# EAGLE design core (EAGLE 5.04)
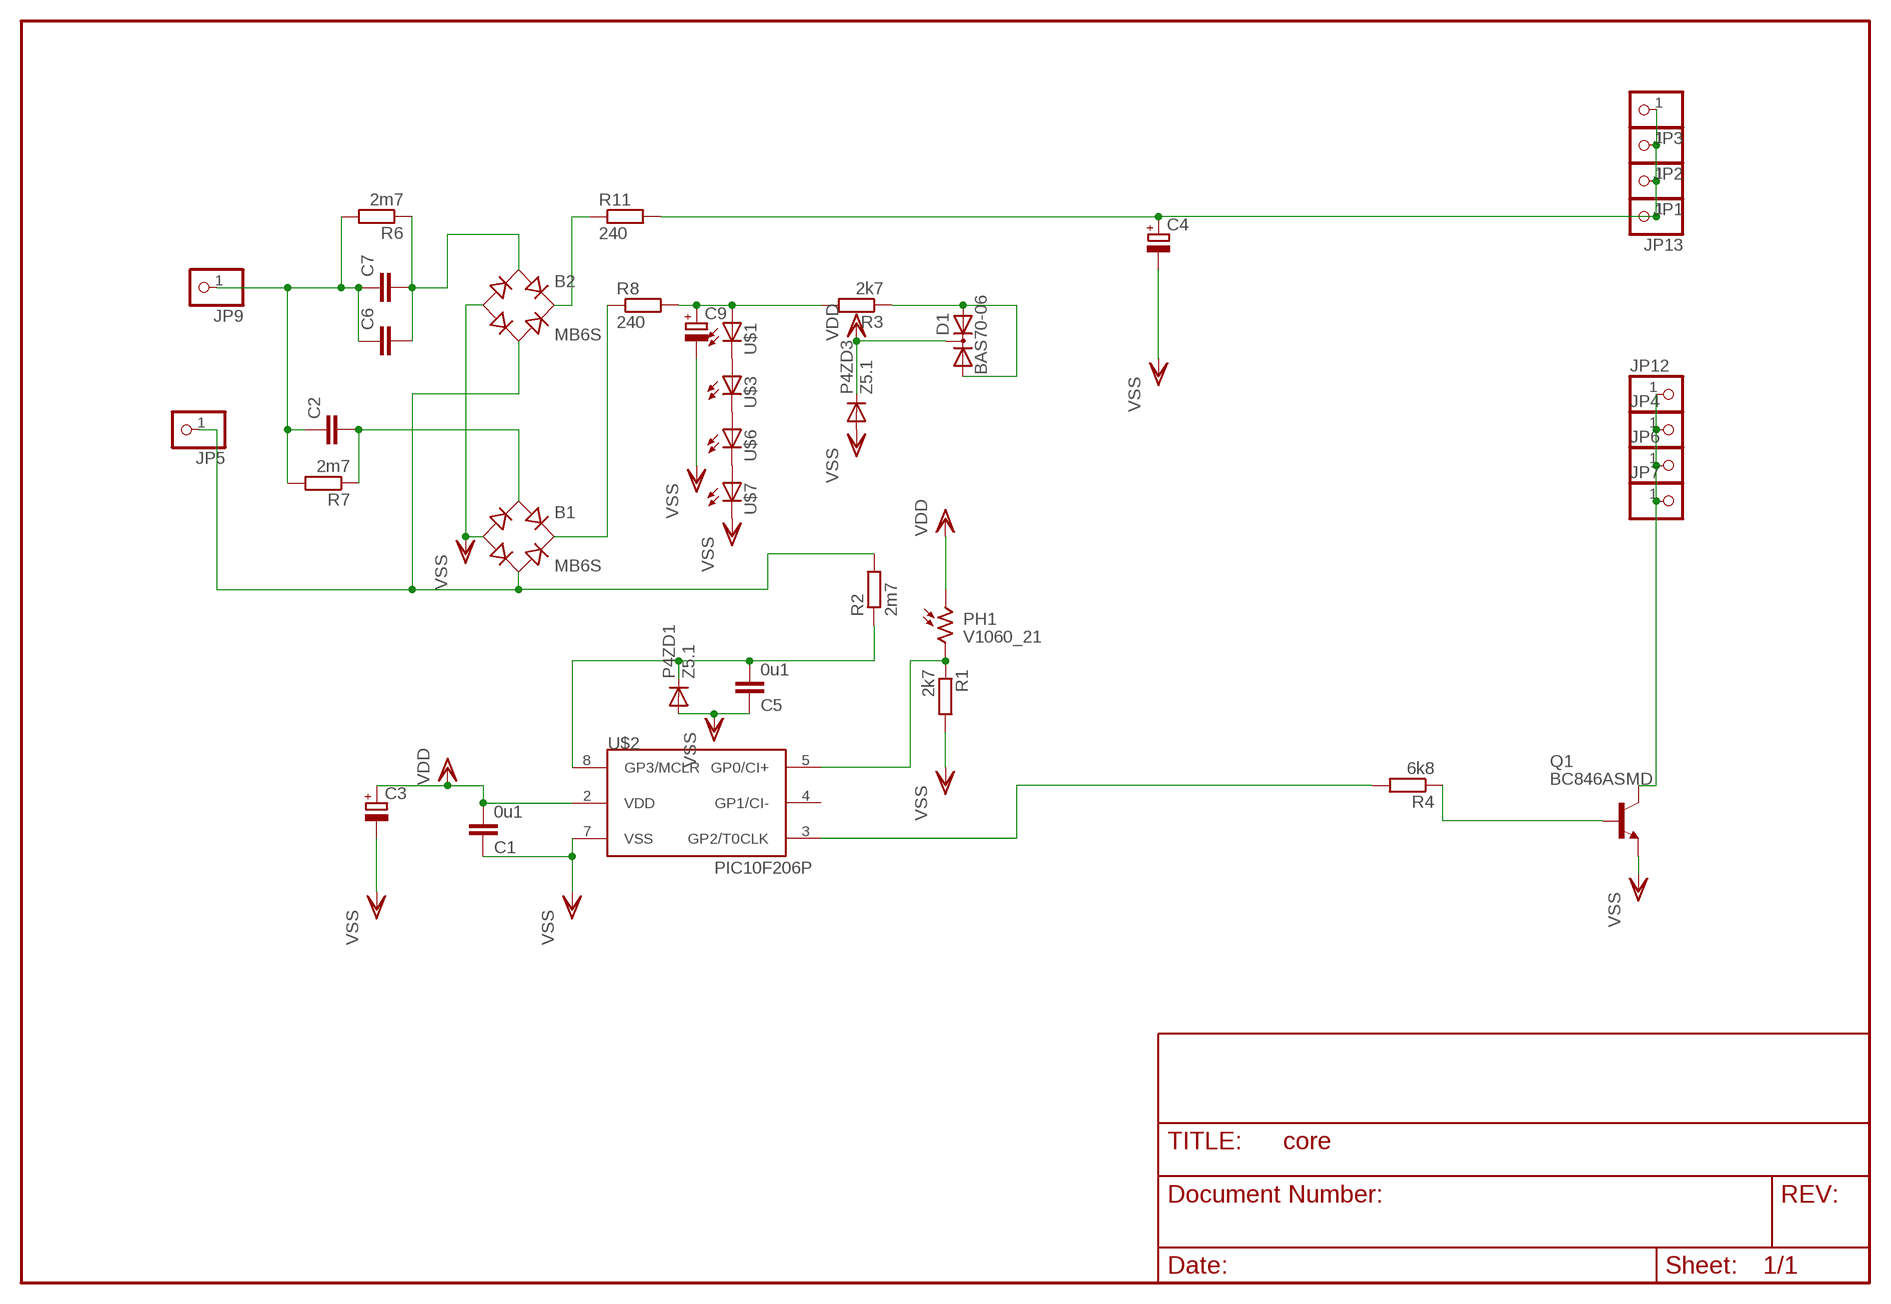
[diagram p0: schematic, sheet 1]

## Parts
B1  MB6S  [SOIC-4]
B2  MB6S  [SOIC-4]
C1  0u1  C-EUC1206  [C1206]
C2  C-EU150-054X183  [C150-054X183]
C3  CPOL-EU5-13  [2,5-5-FLAT]
C4  CPOL-EUTT5D11L  [TT5D11L]
C5  0u1  C-EUC1206  [C1206]
C6  C-EU150-064X183  [C150-064X183]
C7  C-EU150-054X183  [C150-054X183]
C9  CPOL-EUTT5D11L  [TT5D11L]
D1  BAS70-06  [SOT23]
JP1  PINHD-1X1  [1X01]
JP2  PINHD-1X1  [1X01]
JP3  PINHD-1X1  [1X01]
JP4  PINHD-1X1  [1X01]
JP5  PINHD-1X1  [1X01]
JP6  PINHD-1X1  [1X01]
JP7  PINHD-1X1  [1X01]
JP9  PINHD-1X1  [1X01]
JP12  PINHD-1X1  [1X01]
JP13  PINHD-1X1  [1X01]
P4ZD1  Z5.1  DIODE-MINIMELF  [MINIMELF]
P4ZD3  Z5.1  DIODE-MINIMELF  [MINIMELF]
PH1  V1060_21  [TO-5_V10]
Q1  BC846ASMD  [SOT23]
R1  2k7  R-EU_R0805  [R0805]
R2  2m7  R-EU_R1206  [R1206]
R3  2k7  R-EU_R0805  [R0805]
R4  6k8  R-EU_R0805  [R0805]
R6  2m7  R-EU_R1206  [R1206]
R7  2m7  R-EU_R1206  [R1206]
R8  240  R-EU_R1206  [R1206]
R11  240  R-EU_R1206  [R1206]
U$1  LED5MM  [LED5MM]
U$2  PIC10F206P  [DIL8]
U$3  LED5MM  [LED5MM]
U$6  LED5MM  [LED5MM]
U$7  LED5MM  [LED5MM]

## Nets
D+: C4.+ JP1.1 JP2.1 JP3.1 JP13.1 R11.2
D-: JP4.1 JP6.1 JP7.1 JP12.1 Q1.3(C)
N$1: C5.2 P4ZD1.C R2.1 U$2.8(GP3/MCLR)
N$2: B1.+ R8.1
N$3: B1.~2(AC2) B2.~2(AC2) JP5.1 R2.2
N$4: C9.+ R3.2 R8.2 U$1.A
N$5: D1.1(A1) D1.2(A2) R3.1
N$6: C2.1 C6.1 C7.1 JP9.1 R6.2 R7.2
N$7: U$1.K(C) U$3.A
N$8: B1.~1(AC1) C2.2 R7.1
N$9: B2.~1(AC1) C6.2 C7.2 R6.1
N$10: U$3.K(C) U$6.A
N$11: B2.+ R11.1
N$12: Q1.1(B) R4.1
N$15: R4.2 U$2.3(GP2/T0CLK)
N$16: U$6.K(C) U$7.A
N$17: PH1.2 R1.1 U$2.5(GP0/CI+)
VDD: C1.2 C3.+ D1.3(C) P4ZD3.C PH1.1 U$2.2(VDD)
VSS: B1.- B2.- C1.1 C3.- C4.- C5.1 C9.- P4ZD1.A P4ZD3.A Q1.2(E) R1.2 U$2.7(VSS) U$7.K(C)
Unconnected: U$2.4(GP1/CI-)

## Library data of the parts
B1 B2 = rectifier:MB*S: Bridge Rectifier Source: http://www.fairchildsemi.com/ds/MB/MB6S.pdf
C1 C5 = rcl:C-EU: CAPACITOR, European symbol
C2 C6 C7 = rcl-2:C-EU: CAPACITOR, European symbol
C3 C4 C9 = rcl-2:CPOL-EU: POLARIZED CAPACITOR, European symbol
D1 = diode:BAS70-06: Silicon Schottky Diodes General-purpose diode for high-speed switching
JP1-JP7 JP9 JP12 JP13 = pinhead(2):PINHD-1X1: PIN HEADER
P4ZD1 P4ZD3 = diode:DIODE-: DIODE
PH1 = photo-elements:?1060*: Sensor Street Light control
Q1 = transistor-npn:BC846*: NPN Transistor
R1-R4 R6-R8 R11 = rcl-2:R-EU_: RESISTOR, European symbol
U$1 U$3 U$6 U$7 = led(3):LED: LED
U$2 = microchip-3:PIC10F2*: uPC nW 0,25/0,5k Program Flash memory Comparator

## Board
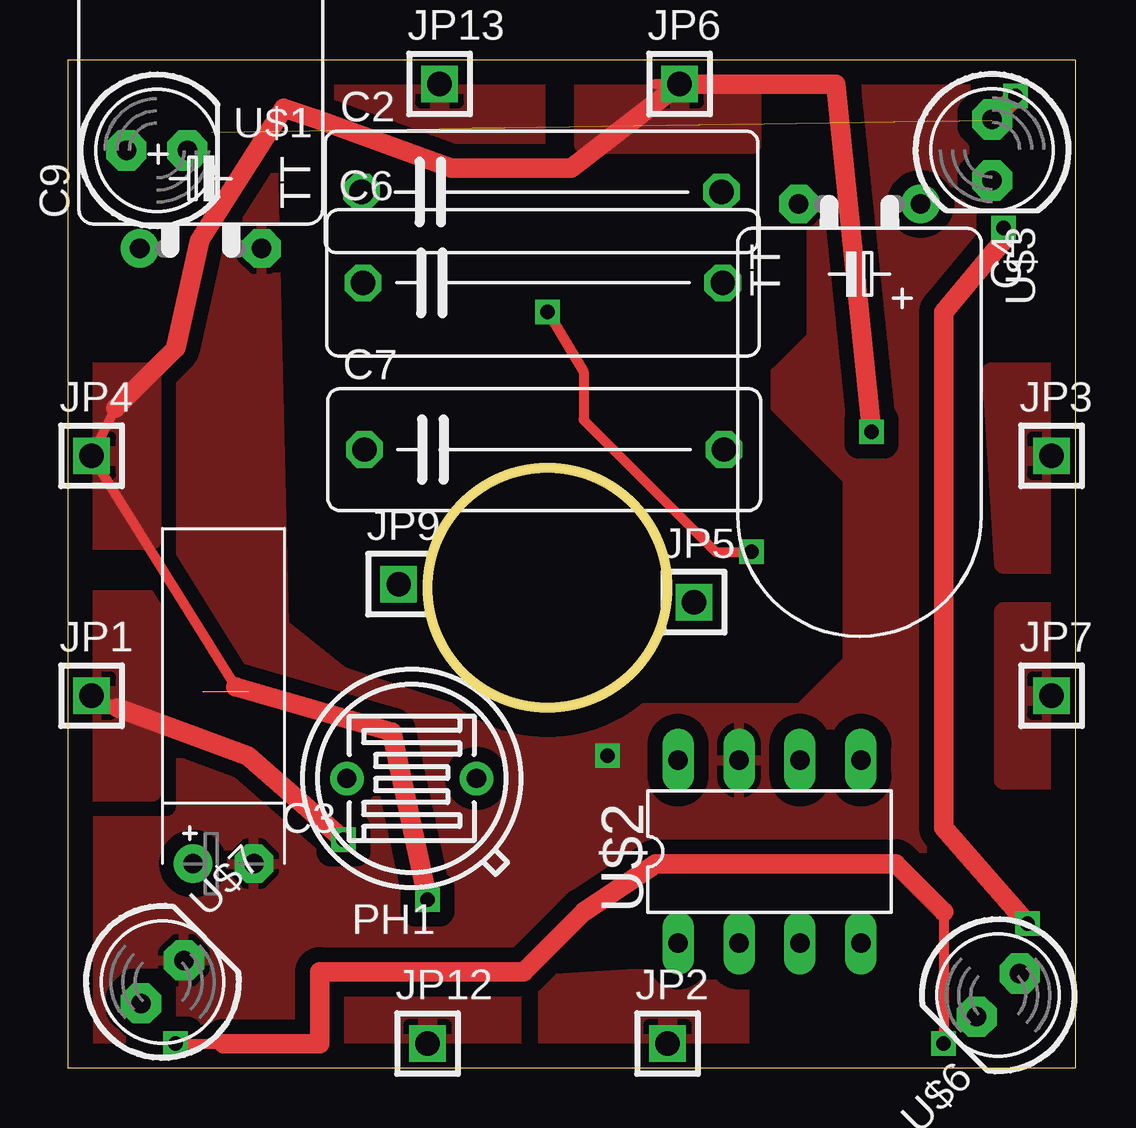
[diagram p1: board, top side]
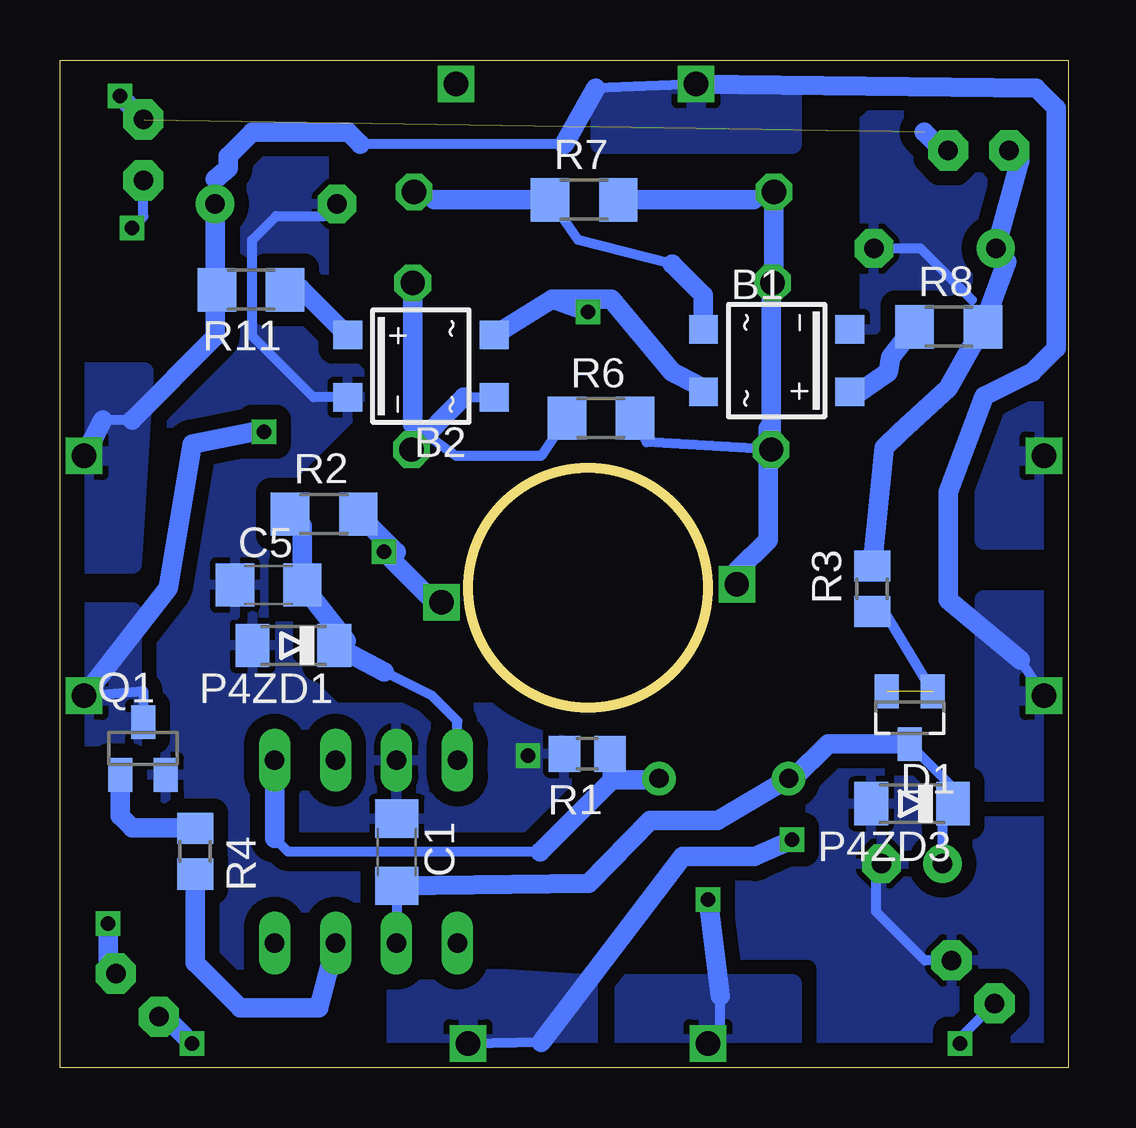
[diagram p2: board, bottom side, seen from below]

Size 42 x 42 mm. Coordinates in mm from the lower left corner, seen from the top.
Outline: 0,0 42,0 42,42 0,42 0,0
Outline: circle at 20,20 radius 5
Copper layers (1*16): Top 0.035mm / dielectric 1.5mm / Bottom 0.035mm
Design rules "default": minimum track width 10mil, minimum drill 24mil, track to track 8mil, track to pad 8mil, pad to pad 8mil, via to via 8mil, smd to smd 8mil, copper to edge 40mil, drill to drill 8mil, minimum pad ring 10mil, minimum via ring 8mil, stop-mask expansion 4mil, vias tented up to drill 0mil, thermal gap 10mil

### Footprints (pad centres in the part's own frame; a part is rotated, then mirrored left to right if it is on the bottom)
SOIC-4 = smd 1.2 x 1.2: + 1.3,3.05; - -1.3,3.05; ~1 -1.3,-3.05; ~2 1.3,-3.05
C1206 = smd 1.6 x 1.8: 1 -1.4,0; 2 1.4,0
C150-054X183 = drill 1.016 octagon: 1 -7.493,0; 2 7.493,0
2,5-5-FLAT = drill 0.813 pad 1.6 round: + -1.27,0 | drill 0.813 pad 1.6 octagon: - 1.27,0
TT5D11L = drill 0.813 pad 1.6 round: + -2.54,0 | drill 0.813 pad 1.6 octagon: - 2.54,0
C150-064X183 = drill 1.016 octagon: 1 -7.493,0; 2 7.493,0
SOT23 = smd 1 x 1.4: 1 -0.95,-1.1; 2 0.95,-1.1; 3 0,1.1
1X01 = drill 1.016 square: 1 0,0
MINIMELF = smd 1.4 x 1.8: A 1.7,0; C -1.7,0
TO-5_V10 = drill 0.8 pad 1.4 round: 1 -2.7,0; 2 2.7,0
R0805 = smd 1.3 x 1.5: 1 -0.95,0; 2 0.95,0
R1206 = smd 1.6 x 1.803: 1 -1.422,0; 2 1.422,0
LED5MM = drill 0.813 pad 1.676 octagon: A -1.27,0; K 1.27,0
DIL8 = drill 0.813 long: 1 -3.81,-3.81; 2 -1.27,-3.81; 3 1.27,-3.81; 4 3.81,-3.81; 5 3.81,3.81; 6 1.27,3.81; 7 -1.27,3.81; 8 -3.81,3.81

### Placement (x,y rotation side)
B1  12.14,29.47 270 bottom
B2  26.96,29.24 90 bottom
C1  27.97,8.97 270 bottom
C2  19.75,36.5 0 top
C3  6.5,8.5 0 top
C4  33,36 180 top
C5  33.31,20.12 0 bottom
C6  19.81,32.71 0 top
C7  19.86,25.76 0 top
C9  5.55,34.14 0 top
D1  6.59,14.58 180 bottom
JP1  1,15.5 0 top
JP2  25,1 0 top
JP3  41,25.5 0 top
JP4  1,25.5 0 top
JP5  26.1,19.4 0 top
JP6  25.5,41 0 top
JP7  41,15.5 0 top
JP9  13.8,20.15 0 top
JP12  15,1 0 top
JP13  15.5,41 0 top
P4ZD1  32.27,17.59 180 bottom
P4ZD3  6.5,11 180 bottom
PH1  14.34,12.05 0 top
Q1  38.54,13.3 0 bottom
R1  20.03,13.08 180 bottom
R2  30.99,23.07 0 bottom
R3  8.16,19.96 90 bottom
R4  36.37,9.01 270 bottom
R6  19.46,27.07 0 bottom
R7  20.16,36.17 0 bottom
R8  4.97,30.88 0 bottom
R11  34.04,32.42 180 bottom
U$1  3.72,38.23 0 top
U$2  29.25,9 0 top
U$3  38.53,38.25 270 top
U$6  38.78,3.02 225 top
U$7  3.96,3.57 45 top

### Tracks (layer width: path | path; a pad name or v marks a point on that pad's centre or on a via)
D+  (via drill 0.6)
  Top 0.406: 2.09,15 JP1.1
  Top 0.813: v11.5,9.5 7.5,13 2.09,15
  Bottom 0.406: 35.54,32.5 R11.2 | 39,27 40.21,27 | 21.94,1.06 JP2.1 | JP1.1 2,17 | JP13.1 19.68,40.82 | 21,38.5 29.5,38.5 | 35.54,37.04 C4.+
  Bottom 0.813: C4.+ 35.54,32.5 35.54,30.46 39,27 | 40.21,27 JP3.1 | 21.94,1.06 16.05,8.8 13.05,8.8 v11.5,9.5 | JP13.1 1.32,40.82 0.5,40 0.5,30 1.5,29 3.5,28 5,24 5,19.5 2,17 | 19.68,40.82 21,38.5 | 35.54,37.04 35,37.5 35,38 34,39 30,39 29.5,38.5
  pour Bottom (isolate 0.61, rank 2): 20,3.5 20,0.5 28,0.5 28,1 28,4
  pour Top (isolate 0.61, rank 2): 20,3.5 20,0.5 28,0.5 28,1 28,4
  pour Top (isolate 0.61, rank 2): 39,21 42,21 42,29 41.5,29 38.5,29
  pour Top (isolate 0.61, rank 2): 0.5,11.5 3.5,11.5 3.5,19.5 3,19.5 0,19.5
  pour Top (isolate 0.61, rank 2): 19.5,38.5 19.5,41.5 11.5,41.5 11.5,41 11.5,38
  pour Bottom (isolate 0.61, rank 2): 19.5,38.5 19.5,41.5 11.5,41.5 11.5,38.5
  pour Bottom (isolate 0.61, rank 2): 39,21 42,21 42,29 41.5,29 38.5,29
  pour Bottom (isolate 0.61, rank 2): 0.5,11.5 3.5,11.5 3.5,19.5 3,19.5 0,19.5
D-  (via drill 0.6)
  Top 0.406: 7,15.86 JP4.1 2,27.5 | JP6.1 24.51,41
  Top 0.813: v15,7 13.5,14 7,15.86 | 2,27.5 4.5,30 5.5,34.5 9,40 10.5,39.5 16,37.5 20.99,37.5 JP6.1 32,41 v33.5,26.5
  Bottom 0.406: JP12.1 14.5,1.5 14.5,3 | v33.5,26.5 34,26.5 | Q1.3 38.54,15.7 JP7.1
  Bottom 0.813: 14.5,3 v15,7 | JP7.1 37.5,20 36.5,26 34,26.5
  pour Bottom (isolate 0.61): 11.5,0 11.5,3.5 18.5,3.5 18.5,0
  pour Top (isolate 0.61): 11.5,0 11.5,3.5 18.5,3.5 18.5,0
  pour Top (isolate 0.61): 42.5,12 39,12 39,19 42.5,19
  pour Top (isolate 0.61): 28.5,42 28.5,38.5 21.5,38.5 21.5,42
  pour Top (isolate 0.61): 3.5,22 0,22 0,29 3.5,29
  pour Bottom (isolate 0.61): 42.5,12 39,12 39,19 42.5,19
  pour Top (isolate 0.61): 28.5,42 28.5,38.5 21.5,38.5 21.5,42
  pour Bottom (isolate 0.61): 3.5,22 0,22 0,29 3.5,29
N$1
  Bottom 0.406: U$2.8 25.44,14.44 26.5,15.5 28.48,16.5 | P4ZD1.C 30.07,17.78 | 31.91,22.57 R2.1
  Bottom 0.813: 28.48,16.5 P4ZD1.C | 30.07,17.78 C5.2 31.91,22.57
N$2
  Bottom 0.406: 8.92,28 B1.+
  Bottom 0.813: R8.1 7.39,29.61 7.5,29 8.92,28
N$3  (via drill 0.6)
  Top 0.406: v28.5,21.5 27,21.5 21.5,27 21.5,29 v20,31.5
  Bottom 0.406: B1.~2 15.52,28.5 | 26.4,19.4 JP5.1 | R2.2 | v28.5,21.5 28,21.5
  Bottom 0.813: 21.5,32.04 19.04,32.04 16.5,29 15.52,28.5 | 21.5,32.04 B2.~2 | v28.5,21.5 26.4,19.4 | 21.5,32.04 v20,31.5 | 28,21.5 R2.2
N$4
  Bottom 0.406: 2.55,33.6 C9.+ | 2.01,37.78 U$1.A
  Bottom 0.813: R3.2 7.67,25.84 7,26.5 5,28.33 R8.2 2.55,33.6 | C9.+ 2.01,37.78
N$5  (1 unrouted)
  Bottom 0.406: D1.1 7.64,18.99 R3.1
N$6
  Bottom 0.406: JP9.1 13.8,20.7 | 12.5,26.63 C7.1 17.56,26.07 R6.2 | 12.37,32.16 C6.1 12.26,32.27 | C2.1 13.09,36.17
  Bottom 0.813: 13.8,20.7 12.5,22 12.5,26.63 | C7.1 12.37,32.16 | 12.26,32.27 C2.1 | 13.09,36.17 R7.2
N$7  (via drill 0.6)  (1 unrouted)
  Top 0.406: U$3.A 38.5,39.5
  Top 0.813: 38.5,39.5 v39.5,40.5
  Bottom 0.813: U$1.K 5.23,38.23 6,39 | v39.5,40.5 38.5,39.5
N$8
  Bottom 0.406: 16.5,33.5 20.41,34.5 R7.1 | 26.41,36.17 C2.2
  Bottom 0.813: B1.~1 15.19,32.19 16.5,33.5 | R7.1 26.41,36.17
N$9
  Bottom 0.406: R6.1 21.95,25.5 25.5,25.5 27.26,26.76 C7.2 27.3,26.81 | 25.17,27.94 B2.~1
  Bottom 0.813: 27.3,26.81 C6.2 | C7.2 25.17,27.94
N$10  (via drill 0.6)
  Top 0.406: 39,34.5 v39,35
  Top 0.813: 39,34.5 36.5,31.5 36.5,10 v40,6
  Bottom 0.406: U$3.K 38.53,35.47 v39,35
  Bottom 0.813: v40,6 40,4.24 U$6.A
N$11
  Bottom 0.406: B2.+ 30.04,30.54 | 32,32.5 32.54,32.5 R11.1
  Bottom 0.813: 30.04,30.54 32,32.5
N$12
  Bottom 0.406: R4.1 36.41,10
  Bottom 0.813: Q1.1 39.49,10.49 39,10 36.41,10
N$15
  Bottom 0.813: R4.2 36.37,4.37 34.5,2.5 31.21,2.5 U$2.3
N$16  (via drill 0.6)
  Top 0.406: 36.5,6.5 v36.5,1 | v4.5,1 6.5,1
  Top 0.813: 36.5,6.5 34.5,8.5 24.5,8.5 21.5,6.5 19,4 10.5,4 10.5,1 6.5,1
  Bottom 0.406: 37.62,2.12 U$6.K | v4.5,1 4.5,1.23 U$7.A
  Bottom 0.813: v36.5,1 37.62,2.12
N$17
  Bottom 0.406: 33.06,9.56 32.5,9 22,9 | PH1.2 17.09,12
  Bottom 0.813: 33.06,9.56 U$2.5 | 19,12 22,9 | 17.09,12 19,12 | 19,12 19,13 R1.1
VDD
  Bottom 0.406: C3.+ 5.23,10.57 P4ZD3.C 4.8,11.68 D1.3 6.62,13.5 | C1.2 27.97,4.53 28,4.5 28,5.17 U$2.2 | 11.45,12.05 PH1.1
  Bottom 0.813: C1.2 19.98,7.67 17.4,10.3 14.59,10.3 PH1.1 | 11.45,12.05 10,13.5 6.62,13.5
VSS  (via drill 0.6)
  Bottom 0.406: B2.- 31.44,27.94 34,30.5 34,34.5 33,35.5 30.96,35.5 C4.- | U$7.K 5.97,4.47 8,6.5 8,8.27 C3.- | C9.- 6.14,34.14 4,32
  other vias: 22.5,13
  pour Bottom (isolate 0.61, rank 5): 1,41 7,41 8.5,39.5 8.5,17 10.5,15 30.5,15 32.5,17 32.5,24.5 29.5,27.5 29.5,29 31,30.5 31,39.5 32.5,41 40.5,41 41,40.5 41,1 40.5,0.5 1.5,0.5 1,1
  pour Top (isolate 0.61, rank 5): 1,41 7,41 8.5,39.5 9,18.5 11.5,16.5 16,15 30.5,15 32.5,17 32.5,24.5 29.5,27.5 29.5,29 31,30.5 31,39.5 32.5,41 40.5,41 41,40.5 41,1 40.5,0.5 1.5,0.5 1,1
